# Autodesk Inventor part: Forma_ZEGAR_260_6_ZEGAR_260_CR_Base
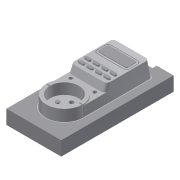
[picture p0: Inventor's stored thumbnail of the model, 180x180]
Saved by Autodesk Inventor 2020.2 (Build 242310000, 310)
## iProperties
Created: 2015-01
Part Number: Forma_ZEGAR_260_6_ZEGAR_260_CR_Base
Material: Ogólny
Document SubType Name: Modeling
Designer: F.Stasiak
Density: 1 g/cm^3
Appearance: Domyślna
Catalog Web Link: www.expertbooks.pl
Manager: www.cadconsulting.pl
Company: Fabian Stasiak CAD Consulting
Author: F.Stasiak
Subject: Zbiór ćwiczeń. Autodesk Inventor 2020. Kurs Professional
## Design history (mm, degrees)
node "Forma_ZEGAR_260_4_ZEGAR_260_MP"
feature "Rzeźbienie1"
feature "Bryła3::Forma_ZEGAR_260_4_ZEGAR_260_MP"
tag "Bryła wyprowadzona1"
node "Bryła1"
feature "Forma_ZEGAR_260_4_ZEGAR_260_MP_Bodies"
feature "Powierzchnia1"
body "Srf1"
